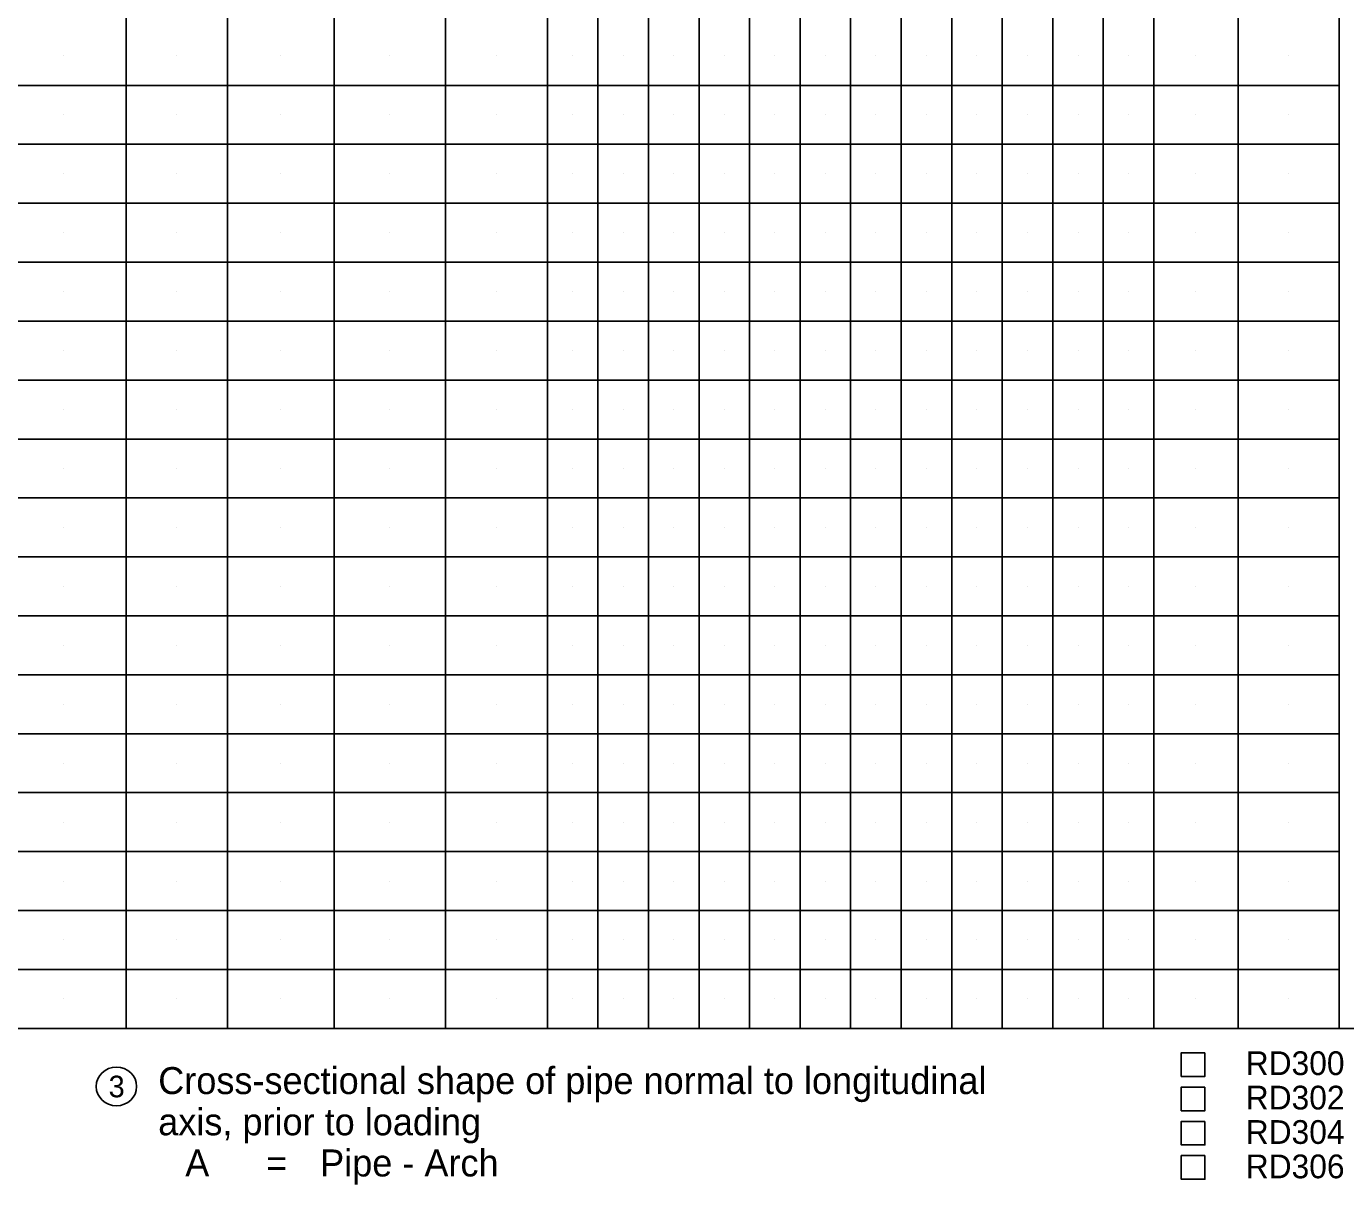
# Model space of a CAD drawing. Extents: x 0 to 1.42, y 0 to 0.92.
# Drawn here: x 0.2562 to 0.5109, y 0.2302 to 0.4539 of the extents above; entities that cross this region are included whole.
import ezdxf

# ---------------------------------------------------------------- set-up
doc = ezdxf.new("R2010")
doc.units = 0
doc.layers.add('P_ODOT_PLAN_General', color=7, linetype='Continuous')
doc.layers.add('P_RDWY_PLAN_NotesTx', color=7, linetype='Continuous')

msp = doc.modelspace()

# ---------------------------------------------------------------- linework, layer by layer
at = {"layer": 'P_ODOT_PLAN_General'}
for p, q in [((0.35681, 0.26037), (0.35681, 0.875)), ((0.50965, 0.26037), (0.50965, 0.875)), ((0.36656, 0.26037), (0.36656, 0.86199)), ((0.37632, 0.26037), (0.37632, 0.86199)), ((0.38608, 0.26037), (0.38608, 0.86199)), ((0.39583, 0.26037), (0.39583, 0.86199)), ((0.40559, 0.26037), (0.40559, 0.86199)), ((0.41534, 0.26037), (0.41534, 0.86199)), ((0.4251, 0.26037), (0.4251, 0.86199)), ((0.43486, 0.26037), (0.43486, 0.86199)), ((0.44461, 0.26037), (0.44461, 0.86199)), ((0.45437, 0.26037), (0.45437, 0.86199)), ((0.46412, 0.26037), (0.46412, 0.86199)), ((0.47388, 0.26037), (0.47388, 0.86199)), ((0.49014, 0.26037), (0.49014, 0.86199)), ((0.27551, 0.26037), (0.27551, 0.84573)), ((0.29502, 0.26037), (0.29502, 0.84573)), ((0.33711, 0.26037), (0.33711, 0.7937)), ((0.31564, 0.26037), (0.31564, 0.76118)), ((0.26331, 0.44818), (0.26331, 0.44818)), ((0.28526, 0.44818), (0.28526, 0.44818)), ((0.30533, 0.44818), (0.30533, 0.44818)), ((0.32637, 0.44818), (0.32637, 0.44818)), ((0.34696, 0.44818), (0.34696, 0.44818)), ((0.36169, 0.44818), (0.36169, 0.44818)), ((0.37144, 0.44818), (0.37144, 0.44818)), ((0.3812, 0.44818), (0.3812, 0.44818)), ((0.39095, 0.44818), (0.39095, 0.44818)), ((0.40071, 0.44818), (0.40071, 0.44818)), ((0.41047, 0.44818), (0.41047, 0.44818)), ((0.42022, 0.44818), (0.42022, 0.44818)), ((0.42998, 0.44818), (0.42998, 0.44818)), ((0.43973, 0.44818), (0.43973, 0.44818)), ((0.44949, 0.44818), (0.44949, 0.44818)), ((0.45925, 0.44818), (0.45925, 0.44818)), ((0.469, 0.44818), (0.469, 0.44818)), ((0.48201, 0.44818), (0.48201, 0.44818)), ((0.4999, 0.44818), (0.4999, 0.44818)), ((0.50965, 0.44248), (0.25112, 0.44248)), ((0.26331, 0.43679), (0.26331, 0.43679)), ((0.28526, 0.43679), (0.28526, 0.43679)), ((0.30533, 0.43679), (0.30533, 0.43679)), ((0.32637, 0.43679), (0.32637, 0.43679)), ((0.34696, 0.43679), (0.34696, 0.43679)), ((0.36169, 0.43679), (0.36169, 0.43679)), ((0.37144, 0.43679), (0.37144, 0.43679)), ((0.3812, 0.43679), (0.3812, 0.43679)), ((0.39095, 0.43679), (0.39095, 0.43679)), ((0.40071, 0.43679), (0.40071, 0.43679)), ((0.41047, 0.43679), (0.41047, 0.43679)), ((0.42022, 0.43679), (0.42022, 0.43679)), ((0.42998, 0.43679), (0.42998, 0.43679)), ((0.43973, 0.43679), (0.43973, 0.43679)), ((0.44949, 0.43679), (0.44949, 0.43679)), ((0.45925, 0.43679), (0.45925, 0.43679)), ((0.469, 0.43679), (0.469, 0.43679)), ((0.48201, 0.43679), (0.48201, 0.43679)), ((0.4999, 0.43679), (0.4999, 0.43679)), ((0.50965, 0.4311), (0.25112, 0.4311)), ((0.26331, 0.42541), (0.26331, 0.42541)), ((0.28526, 0.42541), (0.28526, 0.42541)), ((0.30533, 0.42541), (0.30533, 0.42541)), ((0.32637, 0.42541), (0.32637, 0.42541)), ((0.34696, 0.42541), (0.34696, 0.42541)), ((0.36169, 0.42541), (0.36169, 0.42541)), ((0.37144, 0.42541), (0.37144, 0.42541)), ((0.3812, 0.42541), (0.3812, 0.42541)), ((0.39095, 0.42541), (0.39095, 0.42541)), ((0.40071, 0.42541), (0.40071, 0.42541)), ((0.41047, 0.42541), (0.41047, 0.42541)), ((0.42022, 0.42541), (0.42022, 0.42541)), ((0.42998, 0.42541), (0.42998, 0.42541)), ((0.43973, 0.42541), (0.43973, 0.42541)), ((0.44949, 0.42541), (0.44949, 0.42541)), ((0.45925, 0.42541), (0.45925, 0.42541)), ((0.469, 0.42541), (0.469, 0.42541)), ((0.48201, 0.42541), (0.48201, 0.42541)), ((0.4999, 0.42541), (0.4999, 0.42541)), ((0.50965, 0.41972), (0.25112, 0.41972)), ((0.26331, 0.41403), (0.26331, 0.41403)), ((0.28526, 0.41403), (0.28526, 0.41403)), ((0.30533, 0.41403), (0.30533, 0.41403)), ((0.32637, 0.41403), (0.32637, 0.41403)), ((0.34696, 0.41403), (0.34696, 0.41403)), ((0.36169, 0.41403), (0.36169, 0.41403)), ((0.37144, 0.41403), (0.37144, 0.41403)), ((0.3812, 0.41403), (0.3812, 0.41403)), ((0.39095, 0.41403), (0.39095, 0.41403)), ((0.40071, 0.41403), (0.40071, 0.41403)), ((0.41047, 0.41403), (0.41047, 0.41403)), ((0.42022, 0.41403), (0.42022, 0.41403)), ((0.42998, 0.41403), (0.42998, 0.41403)), ((0.43973, 0.41403), (0.43973, 0.41403)), ((0.44949, 0.41403), (0.44949, 0.41403)), ((0.45925, 0.41403), (0.45925, 0.41403)), ((0.469, 0.41403), (0.469, 0.41403)), ((0.48201, 0.41403), (0.48201, 0.41403)), ((0.4999, 0.41403), (0.4999, 0.41403)), ((0.50965, 0.40834), (0.25112, 0.40834)), ((0.26331, 0.40265), (0.26331, 0.40265)), ((0.28526, 0.40265), (0.28526, 0.40265)), ((0.30533, 0.40265), (0.30533, 0.40265)), ((0.32637, 0.40265), (0.32637, 0.40265)), ((0.34696, 0.40265), (0.34696, 0.40265)), ((0.36169, 0.40265), (0.36169, 0.40265)), ((0.37144, 0.40265), (0.37144, 0.40265)), ((0.3812, 0.40265), (0.3812, 0.40265)), ((0.39095, 0.40265), (0.39095, 0.40265)), ((0.40071, 0.40265), (0.40071, 0.40265)), ((0.41047, 0.40265), (0.41047, 0.40265)), ((0.42022, 0.40265), (0.42022, 0.40265)), ((0.42998, 0.40265), (0.42998, 0.40265)), ((0.43973, 0.40265), (0.43973, 0.40265)), ((0.44949, 0.40265), (0.44949, 0.40265)), ((0.45925, 0.40265), (0.45925, 0.40265)), ((0.469, 0.40265), (0.469, 0.40265)), ((0.48201, 0.40265), (0.48201, 0.40265)), ((0.4999, 0.40265), (0.4999, 0.40265)), ((0.50965, 0.39696), (0.25112, 0.39696)), ((0.26331, 0.39127), (0.26331, 0.39127)), ((0.28526, 0.39127), (0.28526, 0.39127)), ((0.30533, 0.39127), (0.30533, 0.39127)), ((0.32637, 0.39127), (0.32637, 0.39127)), ((0.34696, 0.39127), (0.34696, 0.39127)), ((0.36169, 0.39127), (0.36169, 0.39127)), ((0.37144, 0.39127), (0.37144, 0.39127)), ((0.3812, 0.39127), (0.3812, 0.39127)), ((0.39095, 0.39127), (0.39095, 0.39127)), ((0.40071, 0.39127), (0.40071, 0.39127)), ((0.41047, 0.39127), (0.41047, 0.39127)), ((0.42022, 0.39127), (0.42022, 0.39127)), ((0.42998, 0.39127), (0.42998, 0.39127)), ((0.43973, 0.39127), (0.43973, 0.39127)), ((0.44949, 0.39127), (0.44949, 0.39127)), ((0.45925, 0.39127), (0.45925, 0.39127)), ((0.469, 0.39127), (0.469, 0.39127)), ((0.48201, 0.39127), (0.48201, 0.39127)), ((0.4999, 0.39127), (0.4999, 0.39127)), ((0.50965, 0.38557), (0.25112, 0.38557)), ((0.26331, 0.37988), (0.26331, 0.37988)), ((0.28526, 0.37988), (0.28526, 0.37988)), ((0.30533, 0.37988), (0.30533, 0.37988)), ((0.32637, 0.37988), (0.32637, 0.37988)), ((0.34696, 0.37988), (0.34696, 0.37988)), ((0.36169, 0.37988), (0.36169, 0.37988)), ((0.37144, 0.37988), (0.37144, 0.37988)), ((0.3812, 0.37988), (0.3812, 0.37988)), ((0.39095, 0.37988), (0.39095, 0.37988)), ((0.40071, 0.37988), (0.40071, 0.37988)), ((0.41047, 0.37988), (0.41047, 0.37988)), ((0.42022, 0.37988), (0.42022, 0.37988)), ((0.42998, 0.37988), (0.42998, 0.37988)), ((0.43973, 0.37988), (0.43973, 0.37988)), ((0.44949, 0.37988), (0.44949, 0.37988)), ((0.45925, 0.37988), (0.45925, 0.37988)), ((0.469, 0.37988), (0.469, 0.37988)), ((0.48201, 0.37988), (0.48201, 0.37988)), ((0.4999, 0.37988), (0.4999, 0.37988)), ((0.50965, 0.37419), (0.25112, 0.37419)), ((0.26331, 0.3685), (0.26331, 0.3685)), ((0.28526, 0.3685), (0.28526, 0.3685)), ((0.30533, 0.3685), (0.30533, 0.3685)), ((0.32637, 0.3685), (0.32637, 0.3685)), ((0.34696, 0.3685), (0.34696, 0.3685)), ((0.36169, 0.3685), (0.36169, 0.3685)), ((0.37144, 0.3685), (0.37144, 0.3685)), ((0.3812, 0.3685), (0.3812, 0.3685)), ((0.39095, 0.3685), (0.39095, 0.3685)), ((0.40071, 0.3685), (0.40071, 0.3685)), ((0.41047, 0.3685), (0.41047, 0.3685)), ((0.42022, 0.3685), (0.42022, 0.3685)), ((0.42998, 0.3685), (0.42998, 0.3685)), ((0.43973, 0.3685), (0.43973, 0.3685)), ((0.44949, 0.3685), (0.44949, 0.3685)), ((0.45925, 0.3685), (0.45925, 0.3685)), ((0.469, 0.3685), (0.469, 0.3685)), ((0.48201, 0.3685), (0.48201, 0.3685)), ((0.4999, 0.3685), (0.4999, 0.3685)), ((0.50965, 0.36281), (0.25112, 0.36281)), ((0.26331, 0.35712), (0.26331, 0.35712)), ((0.28526, 0.35712), (0.28526, 0.35712)), ((0.30533, 0.35712), (0.30533, 0.35712)), ((0.32637, 0.35712), (0.32637, 0.35712)), ((0.34696, 0.35712), (0.34696, 0.35712)), ((0.36169, 0.35712), (0.36169, 0.35712)), ((0.37144, 0.35712), (0.37144, 0.35712)), ((0.3812, 0.35712), (0.3812, 0.35712)), ((0.39095, 0.35712), (0.39095, 0.35712)), ((0.40071, 0.35712), (0.40071, 0.35712)), ((0.41047, 0.35712), (0.41047, 0.35712)), ((0.42022, 0.35712), (0.42022, 0.35712)), ((0.42998, 0.35712), (0.42998, 0.35712)), ((0.43973, 0.35712), (0.43973, 0.35712)), ((0.44949, 0.35712), (0.44949, 0.35712)), ((0.45925, 0.35712), (0.45925, 0.35712)), ((0.469, 0.35712), (0.469, 0.35712)), ((0.48201, 0.35712), (0.48201, 0.35712)), ((0.4999, 0.35712), (0.4999, 0.35712)), ((0.50965, 0.35143), (0.25112, 0.35143)), ((0.26331, 0.34574), (0.26331, 0.34574)), ((0.28526, 0.34574), (0.28526, 0.34574)), ((0.30533, 0.34574), (0.30533, 0.34574)), ((0.32637, 0.34574), (0.32637, 0.34574)), ((0.34696, 0.34574), (0.34696, 0.34574)), ((0.36169, 0.34574), (0.36169, 0.34574)), ((0.37144, 0.34574), (0.37144, 0.34574)), ((0.3812, 0.34574), (0.3812, 0.34574)), ((0.39095, 0.34574), (0.39095, 0.34574)), ((0.40071, 0.34574), (0.40071, 0.34574)), ((0.41047, 0.34574), (0.41047, 0.34574)), ((0.42022, 0.34574), (0.42022, 0.34574)), ((0.42998, 0.34574), (0.42998, 0.34574)), ((0.43973, 0.34574), (0.43973, 0.34574)), ((0.44949, 0.34574), (0.44949, 0.34574)), ((0.45925, 0.34574), (0.45925, 0.34574)), ((0.469, 0.34574), (0.469, 0.34574)), ((0.48201, 0.34574), (0.48201, 0.34574)), ((0.4999, 0.34574), (0.4999, 0.34574)), ((0.50965, 0.34005), (0.25112, 0.34005)), ((0.26331, 0.33436), (0.26331, 0.33436)), ((0.28526, 0.33436), (0.28526, 0.33436)), ((0.30533, 0.33436), (0.30533, 0.33436)), ((0.32637, 0.33436), (0.32637, 0.33436)), ((0.34696, 0.33436), (0.34696, 0.33436)), ((0.36169, 0.33436), (0.36169, 0.33436)), ((0.37144, 0.33436), (0.37144, 0.33436)), ((0.3812, 0.33436), (0.3812, 0.33436)), ((0.39095, 0.33436), (0.39095, 0.33436)), ((0.40071, 0.33436), (0.40071, 0.33436)), ((0.41047, 0.33436), (0.41047, 0.33436)), ((0.42022, 0.33436), (0.42022, 0.33436)), ((0.42998, 0.33436), (0.42998, 0.33436)), ((0.43973, 0.33436), (0.43973, 0.33436)), ((0.44949, 0.33436), (0.44949, 0.33436)), ((0.45925, 0.33436), (0.45925, 0.33436)), ((0.469, 0.33436), (0.469, 0.33436)), ((0.48201, 0.33436), (0.48201, 0.33436)), ((0.4999, 0.33436), (0.4999, 0.33436)), ((0.50965, 0.32866), (0.25112, 0.32866)), ((0.26331, 0.32297), (0.26331, 0.32297)), ((0.28526, 0.32297), (0.28526, 0.32297)), ((0.30533, 0.32297), (0.30533, 0.32297)), ((0.32637, 0.32297), (0.32637, 0.32297)), ((0.34696, 0.32297), (0.34696, 0.32297)), ((0.36169, 0.32297), (0.36169, 0.32297)), ((0.37144, 0.32297), (0.37144, 0.32297)), ((0.3812, 0.32297), (0.3812, 0.32297)), ((0.39095, 0.32297), (0.39095, 0.32297)), ((0.40071, 0.32297), (0.40071, 0.32297)), ((0.41047, 0.32297), (0.41047, 0.32297)), ((0.42022, 0.32297), (0.42022, 0.32297)), ((0.42998, 0.32297), (0.42998, 0.32297)), ((0.43973, 0.32297), (0.43973, 0.32297)), ((0.44949, 0.32297), (0.44949, 0.32297)), ((0.45925, 0.32297), (0.45925, 0.32297)), ((0.469, 0.32297), (0.469, 0.32297)), ((0.48201, 0.32297), (0.48201, 0.32297)), ((0.4999, 0.32297), (0.4999, 0.32297)), ((0.50965, 0.31728), (0.25112, 0.31728)), ((0.26331, 0.31159), (0.26331, 0.31159)), ((0.28526, 0.31159), (0.28526, 0.31159)), ((0.30533, 0.31159), (0.30533, 0.31159)), ((0.32637, 0.31159), (0.32637, 0.31159)), ((0.34696, 0.31159), (0.34696, 0.31159)), ((0.36169, 0.31159), (0.36169, 0.31159)), ((0.37144, 0.31159), (0.37144, 0.31159)), ((0.3812, 0.31159), (0.3812, 0.31159)), ((0.39095, 0.31159), (0.39095, 0.31159)), ((0.40071, 0.31159), (0.40071, 0.31159)), ((0.41047, 0.31159), (0.41047, 0.31159)), ((0.42022, 0.31159), (0.42022, 0.31159)), ((0.42998, 0.31159), (0.42998, 0.31159)), ((0.43973, 0.31159), (0.43973, 0.31159)), ((0.44949, 0.31159), (0.44949, 0.31159)), ((0.45925, 0.31159), (0.45925, 0.31159)), ((0.469, 0.31159), (0.469, 0.31159)), ((0.48201, 0.31159), (0.48201, 0.31159)), ((0.4999, 0.31159), (0.4999, 0.31159)), ((0.50965, 0.3059), (0.25112, 0.3059)), ((0.26331, 0.30021), (0.26331, 0.30021)), ((0.28526, 0.30021), (0.28526, 0.30021)), ((0.30533, 0.30021), (0.30533, 0.30021)), ((0.32637, 0.30021), (0.32637, 0.30021)), ((0.34696, 0.30021), (0.34696, 0.30021)), ((0.36169, 0.30021), (0.36169, 0.30021)), ((0.37144, 0.30021), (0.37144, 0.30021)), ((0.3812, 0.30021), (0.3812, 0.30021)), ((0.39095, 0.30021), (0.39095, 0.30021)), ((0.40071, 0.30021), (0.40071, 0.30021)), ((0.41047, 0.30021), (0.41047, 0.30021)), ((0.42022, 0.30021), (0.42022, 0.30021)), ((0.42998, 0.30021), (0.42998, 0.30021)), ((0.43973, 0.30021), (0.43973, 0.30021)), ((0.44949, 0.30021), (0.44949, 0.30021)), ((0.45925, 0.30021), (0.45925, 0.30021)), ((0.469, 0.30021), (0.469, 0.30021)), ((0.48201, 0.30021), (0.48201, 0.30021)), ((0.4999, 0.30021), (0.4999, 0.30021)), ((0.50965, 0.29452), (0.25112, 0.29452)), ((0.26331, 0.28883), (0.26331, 0.28883)), ((0.28526, 0.28883), (0.28526, 0.28883)), ((0.30533, 0.28883), (0.30533, 0.28883)), ((0.32637, 0.28883), (0.32637, 0.28883)), ((0.34696, 0.28883), (0.34696, 0.28883)), ((0.36169, 0.28883), (0.36169, 0.28883)), ((0.37144, 0.28883), (0.37144, 0.28883)), ((0.3812, 0.28883), (0.3812, 0.28883)), ((0.39095, 0.28883), (0.39095, 0.28883)), ((0.40071, 0.28883), (0.40071, 0.28883)), ((0.41047, 0.28883), (0.41047, 0.28883)), ((0.42022, 0.28883), (0.42022, 0.28883)), ((0.42998, 0.28883), (0.42998, 0.28883)), ((0.43973, 0.28883), (0.43973, 0.28883)), ((0.44949, 0.28883), (0.44949, 0.28883)), ((0.45925, 0.28883), (0.45925, 0.28883)), ((0.469, 0.28883), (0.469, 0.28883)), ((0.48201, 0.28883), (0.48201, 0.28883)), ((0.4999, 0.28883), (0.4999, 0.28883)), ((0.50965, 0.28314), (0.25112, 0.28314)), ((0.26331, 0.27745), (0.26331, 0.27745)), ((0.28526, 0.27745), (0.28526, 0.27745)), ((0.30533, 0.27745), (0.30533, 0.27745)), ((0.32637, 0.27745), (0.32637, 0.27745)), ((0.34696, 0.27745), (0.34696, 0.27745)), ((0.36169, 0.27745), (0.36169, 0.27745)), ((0.37144, 0.27745), (0.37144, 0.27745)), ((0.3812, 0.27745), (0.3812, 0.27745)), ((0.39095, 0.27745), (0.39095, 0.27745)), ((0.40071, 0.27745), (0.40071, 0.27745)), ((0.41047, 0.27745), (0.41047, 0.27745)), ((0.42022, 0.27745), (0.42022, 0.27745)), ((0.42998, 0.27745), (0.42998, 0.27745)), ((0.43973, 0.27745), (0.43973, 0.27745)), ((0.44949, 0.27745), (0.44949, 0.27745)), ((0.45925, 0.27745), (0.45925, 0.27745)), ((0.469, 0.27745), (0.469, 0.27745)), ((0.48201, 0.27745), (0.48201, 0.27745)), ((0.4999, 0.27745), (0.4999, 0.27745)), ((0.50965, 0.27175), (0.25112, 0.27175)), ((0.26331, 0.26606), (0.26331, 0.26606)), ((0.28526, 0.26606), (0.28526, 0.26606)), ((0.30533, 0.26606), (0.30533, 0.26606)), ((0.32637, 0.26606), (0.32637, 0.26606)), ((0.34696, 0.26606), (0.34696, 0.26606)), ((0.36169, 0.26606), (0.36169, 0.26606)), ((0.37144, 0.26606), (0.37144, 0.26606)), ((0.3812, 0.26606), (0.3812, 0.26606)), ((0.39095, 0.26606), (0.39095, 0.26606)), ((0.40071, 0.26606), (0.40071, 0.26606)), ((0.41047, 0.26606), (0.41047, 0.26606)), ((0.42022, 0.26606), (0.42022, 0.26606)), ((0.42998, 0.26606), (0.42998, 0.26606)), ((0.43973, 0.26606), (0.43973, 0.26606)), ((0.44949, 0.26606), (0.44949, 0.26606)), ((0.45925, 0.26606), (0.45925, 0.26606)), ((0.469, 0.26606), (0.469, 0.26606)), ((0.48201, 0.26606), (0.48201, 0.26606)), ((0.4999, 0.26606), (0.4999, 0.26606)), ((1.39582, 0.26037), (0.0625, 0.26037)), ((1.39582, 0.26037), (0.0625, 0.26037))]:
    msp.add_line(p, q, dxfattribs=at)
at = {"layer": 'P_RDWY_PLAN_NotesTx'}
for points in [[(0.48373, 0.25567), (0.47917, 0.25567), (0.47917, 0.25111), (0.48373, 0.25111)], [(0.48373, 0.24905), (0.47917, 0.24905), (0.47917, 0.24449), (0.48373, 0.24449)], [(0.48373, 0.24243), (0.47917, 0.24243), (0.47917, 0.23787), (0.48373, 0.23787)], [(0.48373, 0.23581), (0.47917, 0.23581), (0.47917, 0.23125), (0.48373, 0.23125)]]:
    msp.add_lwpolyline(points, close=True, dxfattribs=at)
msp.add_ellipse((0.27361, 0.24917), major_axis=(0.0039, 0), ratio=0.960077, dxfattribs=at)

# ---------------------------------------------------------------- texts
for s, height, p in [('RD300', 0.004583, (0.49161, 0.25137)), ('Cross-sectional shape of pipe normal to longitudinal', 0.0052083, (0.28168, 0.2477)), ('3', 0.00417, (0.2721, 0.24708)), ('RD302', 0.004583, (0.49161, 0.24473)), ('axis, prior to loading', 0.0052083, (0.28168, 0.23974)), ('RD304', 0.004583, (0.49161, 0.23808)), ('A', 0.00521, (0.28689, 0.23179)), ('Pipe - Arch', 0.0052083, (0.31293, 0.23179)), ('=', 0.00521, (0.30251, 0.23179)), ('RD306', 0.004583, (0.49161, 0.23144))]:
    msp.add_text(s, height=height, dxfattribs=at).set_placement(p)

doc.saveas('drawing.dxf')
